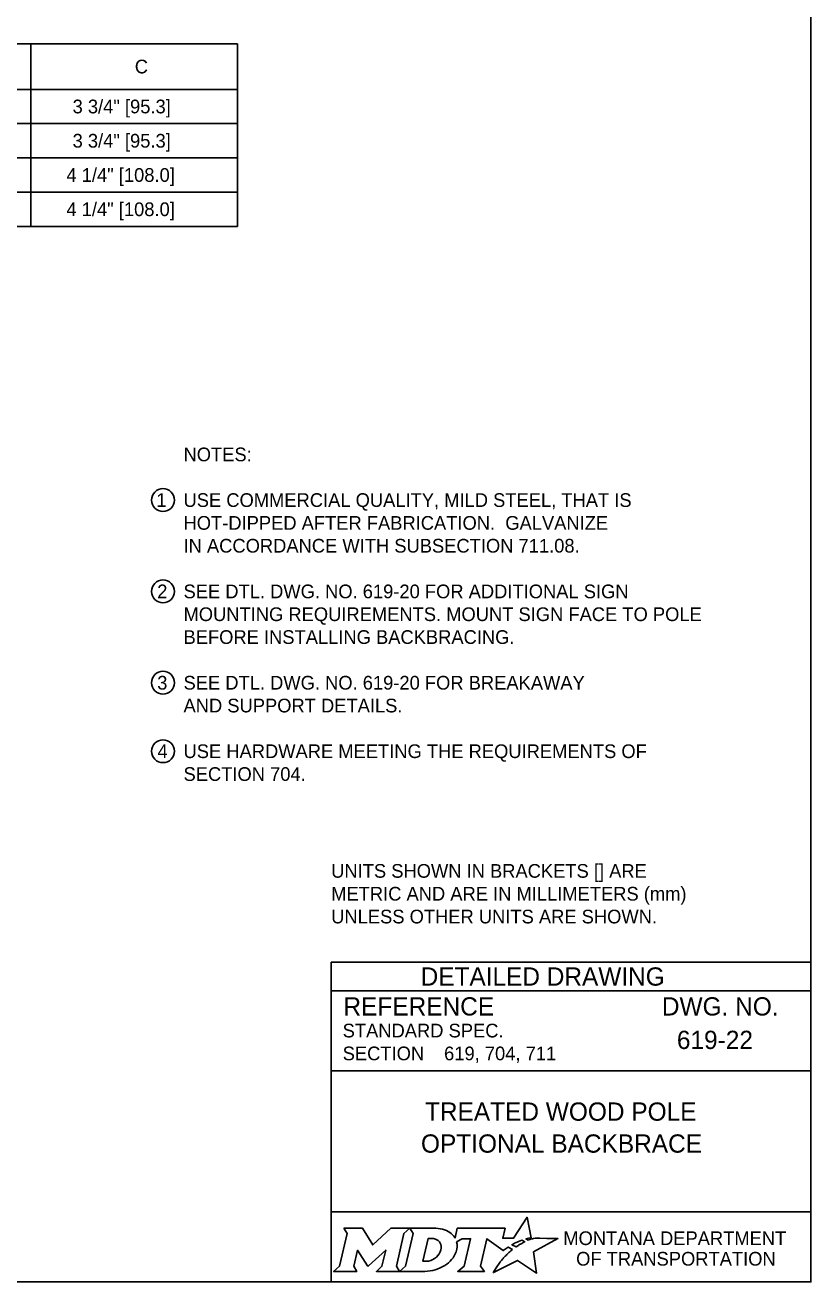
# Model space of a CAD drawing. Extents: x 49991.4 to 50021, y 49987.6 to 50011.4.
# Drawn here: x 50005.17 to 50008.61, y 50000.06 to 50005.57 of the extents above; entities that cross this region are included whole.
import ezdxf

# ---------------------------------------------------------------- set-up
doc = ezdxf.new("R2010")
doc.units = 0
doc.layers.add('Level 1', color=7, linetype='Continuous')
doc.layers.add('Level 2', color=7, linetype='Continuous')

msp = doc.modelspace()

# ---------------------------------------------------------------- linework, layer by layer
at = {"layer": 'Level 1'}
msp.add_lwpolyline([(50008.6146, 50011.2628), (50000.3356, 50011.2628), (50000.3356, 50000.0624), (50008.6146, 50000.0624)], close=True, dxfattribs=at)
at = {"layer": 'Level 2'}
for p, q in [((50002.8458, 50005.4855), (50006.1044, 50005.4855)), ((50005.199, 50004.6855), (50005.199, 50005.4855)), ((50006.1044, 50004.6855), (50006.1044, 50005.4855)), ((50002.8458, 50005.2855), (50006.1044, 50005.2855)), ((50002.8458, 50005.1355), (50006.1044, 50005.1355)), ((50002.8458, 50004.9855), (50006.1044, 50004.9855)), ((50002.8458, 50004.8355), (50006.1044, 50004.8355)), ((50002.8458, 50004.6855), (50006.1044, 50004.6855)), ((50008.6146, 50001.4624), (50006.5146, 50001.4624)), ((50006.5146, 50001.4624), (50006.5146, 50000.0624)), ((50008.6146, 50001.3374), (50006.5146, 50001.3374)), ((50008.2507, 50001.1223), (50008.2507, 50001.1223)), ((50007.0089, 50001.0629), (50007.0089, 50001.0629)), ((50008.6146, 50000.9874), (50006.5146, 50000.9874)), ((50007.5646, 50000.7383), (50007.5646, 50000.7383)), ((50008.6146, 50000.3693), (50006.5146, 50000.3693))]:
    msp.add_line(p, q, dxfattribs=at)
for points in [[(50007.3771, 50000.2447), (50007.3668, 50000.2503), (50007.3784, 50000.2531), (50007.39, 50000.2551), (50007.3726, 50000.3452), (50007.3131, 50000.2539), (50007.2658, 50000.2532), (50007.2761, 50000.2973), (50007.0669, 50000.2974), (50007.0568, 50000.2549), (50007.051, 50000.2632)], [(50006.5701, 50000.2974), (50006.5842, 50000.274), (50006.5507, 50000.1307), (50006.525, 50000.1082), (50006.6266, 50000.1082), (50006.6131, 50000.131), (50006.6293, 50000.2011), (50006.673, 50000.1321), (50006.6783, 50000.1321), (50006.7534, 50000.2016), (50006.737, 50000.1305), (50006.7123, 50000.1085), (50006.8139, 50000.1085), (50006.8001, 50000.1318), (50006.8333, 50000.2742)], [(50006.8333, 50000.2742), (50006.8586, 50000.2974), (50006.7762, 50000.2974), (50006.6966, 50000.2244), (50006.6521, 50000.2971), (50006.5701, 50000.2974)], [(50006.9722, 50000.2974), (50006.8586, 50000.2974), (50006.8733, 50000.2745), (50006.8394, 50000.1307), (50006.8139, 50000.1085), (50006.9245, 50000.1085)], [(50006.9962, 50000.2107), (50006.995, 50000.2026), (50006.9918, 50000.1933), (50006.9876, 50000.1851), (50006.982, 50000.1776), (50006.9755, 50000.1707), (50006.9676, 50000.1644), (50006.9593, 50000.1597), (50006.9502, 50000.1558), (50006.9411, 50000.1535), (50006.9319, 50000.1526), (50006.916, 50000.1526), (50006.9396, 50000.2526), (50006.9556, 50000.2526), (50006.9632, 50000.252), (50006.9708, 50000.2501), (50006.9774, 50000.2471), (50006.9835, 50000.2429), (50006.9883, 50000.2379), (50006.992, 50000.2319), (50006.9947, 50000.2257), (50006.9963, 50000.2183), (50006.9963, 50000.2153), (50006.9962, 50000.2107)], [(50007.0636, 50000.2383), (50007.0882, 50000.2514), (50007.1251, 50000.2514), (50007.0965, 50000.1309), (50007.069, 50000.1082), (50007.1852, 50000.1082), (50007.1682, 50000.1311), (50007.1964, 50000.2513), (50007.2677, 50000.1996), (50007.2888, 50000.2147), (50007.3085, 50000.2038)], [(50007.2527, 50000.1479), (50007.2374, 50000.1235), (50007.2327, 50000.116), (50007.2269, 50000.1074), (50007.2246, 50000.1031), (50007.3299, 50000.1562), (50007.4138, 50000.1011), (50007.4007, 50000.1938), (50007.5076, 50000.2522), (50007.4583, 50000.253), (50007.4282, 50000.2534), (50007.4074, 50000.2537), (50007.4006, 50000.2522), (50007.3957, 50000.251), (50007.3873, 50000.2487), (50007.3771, 50000.2447)], [(50007.3267, 50000.2171), (50007.3243, 50000.2154), (50007.306, 50000.225), (50007.3163, 50000.2307), (50007.3204, 50000.2329), (50007.329, 50000.2369), (50007.3347, 50000.2395), (50007.3426, 50000.2425), (50007.3499, 50000.2452), (50007.3617, 50000.2378), (50007.3577, 50000.2357), (50007.3531, 50000.2332), (50007.3489, 50000.231), (50007.3439, 50000.2281), (50007.342, 50000.227), (50007.3393, 50000.2254), (50007.3368, 50000.224), (50007.3345, 50000.2224), (50007.3319, 50000.2206), (50007.3292, 50000.2188), (50007.3267, 50000.2171)], [(50007.2666, 50000.164), (50007.2666, 50000.164)], [(50006.9702, 50000.1158), (50006.9786, 50000.1184), (50006.9916, 50000.1238), (50007.012, 50000.1348)]]:
    msp.add_lwpolyline(points, dxfattribs=at)
for centre in [(50005.7782, 50003.4866), (50005.7782, 50003.0866), (50005.7782, 50002.6866), (50005.7782, 50002.3866)]:
    msp.add_circle(centre, 0.05, dxfattribs=at)
for centre, radius, start, end in [((50006.9953, 50000.219), 0.0709, 339.5329, 15.8582), ((50006.9513, 50000.2363), 0.1183, 300.9103, 339.1383)]:
    msp.add_arc(centre, radius, start, end, dxfattribs=at)
for centre, major_axis, ratio, start_param, end_param in [((50006.9701, 50000.25), (0.0834, -0.0037), 0.568097, 0.61298, 1.570796), ((50007.0257, 50000.2573), (0.0361, -0.0295), 0.469099, 1.225588, 1.570796), ((50007.2974, 50000.1941), (-0.0112, -0.0097), 0.021651, 3.157348, 6.283185), ((50007.2597, 50000.1559), (-0.00694, -0.00806), 0.008222, 0, 3.137361), ((50007.2764, 50000.1742), (-0.0098, -0.0102), 0.016458, 3.141593, 6.279097), ((50006.9248, 50000.2568), (0, 0.1484), 0.987302, 3.139398, 3.456847)]:
    msp.add_ellipse(centre, major_axis=major_axis, ratio=ratio, start_param=start_param, end_param=end_param, dxfattribs=at)

# ---------------------------------------------------------------- texts
for s, height, p in [('C', 0.06, (50005.6549, 50005.3555)), ('3 3/4" [95.3]', 0.06, (50005.3825, 50005.1805)), ('3 3/4" [95.3]', 0.06, (50005.3825, 50005.0305)), ('4 1/4" [108.0]', 0.06, (50005.3556, 50004.8805)), ('4 1/4" [108.0]', 0.06, (50005.3556, 50004.7305)), ('NOTES:', 0.06, (50005.8682, 50003.6566)), ('1', 0.06, (50005.749, 50003.4566)), ('USE COMMERCIAL QUALITY, MILD STEEL, THAT IS', 0.06, (50005.8682, 50003.4566)), ('HOT-DIPPED AFTER FABRICATION.  GALVANIZE', 0.06, (50005.8682, 50003.3566)), ('IN ACCORDANCE WITH SUBSECTION 711.08.', 0.06, (50005.8682, 50003.2566)), ('2', 0.06, (50005.753, 50003.0566)), ('SEE DTL. DWG. NO. 619-20 FOR ADDITIONAL SIGN', 0.06, (50005.8682, 50003.0566)), ('MOUNTING REQUIREMENTS. MOUNT SIGN FACE TO POLE', 0.06, (50005.8682, 50002.9566)), ('BEFORE INSTALLING BACKBRACING.', 0.06, (50005.8682, 50002.8566)), ('3', 0.06, (50005.753, 50002.6566)), ('SEE DTL. DWG. NO. 619-20 FOR BREAKAWAY', 0.06, (50005.8682, 50002.6566)), ('AND SUPPORT DETAILS.', 0.06, (50005.8682, 50002.5566)), ('4', 0.06, (50005.7542, 50002.3566)), ('USE HARDWARE MEETING THE REQUIREMENTS OF ', 0.06, (50005.8682, 50002.3566)), ('SECTION 704.', 0.06, (50005.8682, 50002.2566)), ('UNITS SHOWN IN BRACKETS [] ARE ', 0.06, (50006.5146, 50001.8324)), ('METRIC AND ARE IN MILLIMETERS (mm) ', 0.06, (50006.5146, 50001.7324)), ('UNLESS OTHER UNITS ARE SHOWN.', 0.06, (50006.5146, 50001.6324)), ('DETAILED DRAWING', 0.0799, (50006.9063, 50001.3599)), ('REFERENCE', 0.08, (50006.5682, 50001.229)), ('DWG. NO.', 0.08, (50007.9624, 50001.229)), ('STANDARD SPEC.', 0.06, (50006.5649, 50001.133)), ('619-22', 0.08, (50008.0281, 50001.0823)), ('SECTION', 0.06, (50006.5649, 50001.033)), ('619, 704, 711', 0.06, (50007.0089, 50001.0329)), ('TREATED WOOD POLE', 0.08, (50006.9252, 50000.7683)), ('OPTIONAL BACKBRACE', 0.08, (50006.9077, 50000.6283)), ('MONTANA DEPARTMENT', 0.06, (50007.5308, 50000.2236)), ('OF TRANSPORTATION', 0.06, (50007.587, 50000.1336))]:
    msp.add_text(s, height=height, dxfattribs=at).set_placement(p)

doc.saveas('drawing.dxf')
